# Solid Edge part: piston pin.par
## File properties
Author: Robert a Rhodes jr
Template: Normal.par
Last saved by: CADCIM
Revision: 14
Application: Solid Edge
Accuracy: 0.99
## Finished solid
Body 1: solid body, 4 faces, 4 edges, 0 vertices.
  Faces by surface: cylinder 2, plane 2
  Edges by curve: circle 4
Bounding box of the edges (mm): 22.000 x 22.000 x 80.000, from (-11, -11, -80) to (11, 11, 0).
Cylindrical faces by radius (mm): R5.5 x1, R11 x1
Planar faces by outward normal: +z 1, -z 1
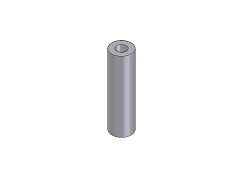
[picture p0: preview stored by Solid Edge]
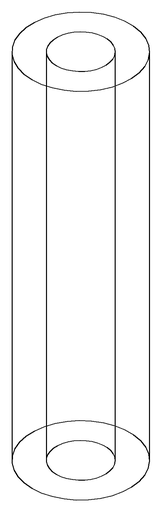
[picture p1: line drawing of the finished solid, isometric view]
